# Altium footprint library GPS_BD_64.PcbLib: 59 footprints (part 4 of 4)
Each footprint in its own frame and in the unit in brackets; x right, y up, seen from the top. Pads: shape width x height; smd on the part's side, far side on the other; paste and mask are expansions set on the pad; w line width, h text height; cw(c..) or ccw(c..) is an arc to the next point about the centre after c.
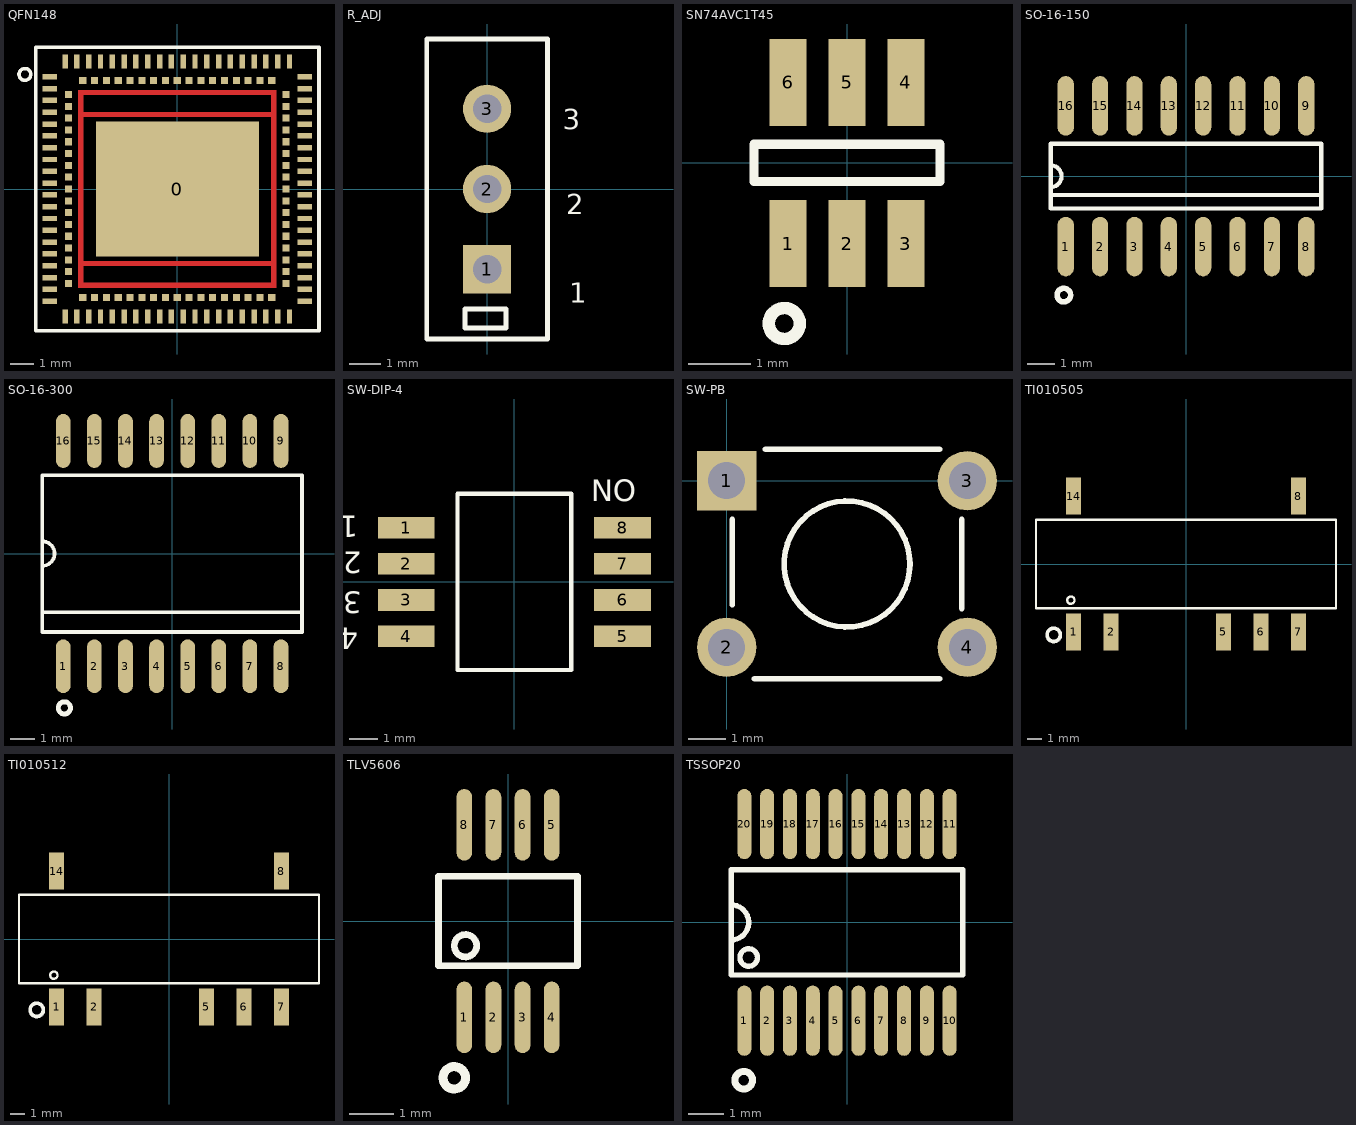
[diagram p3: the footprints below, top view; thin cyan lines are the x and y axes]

## QFN148 [mm]
height 11
pads (149):
  rect 6.9x5.7 smd: 0(0,0)
  rect 0.6x0.23 smd: A1(-5.4,4.75) A2(-5.4,4.25) A3(-5.4,3.75) A4(-5.4,3.25) A5(-5.4,2.75) A6(-5.4,2.25) A7(-5.4,1.75) A8(-5.4,1.25) A9(-5.4,0.75) A10(-5.4,0.25) A11(-5.4,-0.25) A12(-5.4,-0.75) A13(-5.4,-1.25) A14(-5.4,-1.75) A15(-5.4,-2.25) A16(-5.4,-2.75) A17(-5.4,-3.25) A18(-5.4,-3.75) A19(-5.4,-4.25) A20(-5.4,-4.75) A41(5.4,-4.75) A42(5.4,-4.25) A43(5.4,-3.75) A44(5.4,-3.25) A45(5.4,-2.75) A46(5.4,-2.25) A47(5.4,-1.75) A48(5.4,-1.25) A49(5.4,-0.75) A50(5.4,-0.25) A51(5.4,0.25) A52(5.4,0.75) A53(5.4,1.25) A54(5.4,1.75) A55(5.4,2.25) A56(5.4,2.75) A57(5.4,3.25) A58(5.4,3.75) A59(5.4,4.25) A60(5.4,4.75)
  rect 0.23x0.6 smd: A21(-4.75,-5.4) A22(-4.25,-5.4) A23(-3.75,-5.4) A24(-3.25,-5.4) A25(-2.75,-5.4) A26(-2.25,-5.4) A27(-1.75,-5.4) A28(-1.25,-5.4) A29(-0.75,-5.4) A30(-0.25,-5.4) A31(0.25,-5.4) A32(0.75,-5.4) A33(1.25,-5.4) A34(1.75,-5.4) A35(2.25,-5.4) A36(2.75,-5.4) A37(3.25,-5.4) A38(3.75,-5.4) A39(4.25,-5.4) A40(4.75,-5.4) A61(4.75,5.4) A62(4.25,5.4) A63(3.75,5.4) A64(3.25,5.4) A65(2.75,5.4) A66(2.25,5.4) A67(1.75,5.4) A68(1.25,5.4) A69(0.75,5.4) A70(0.25,5.4) A71(-0.25,5.4) A72(-0.75,5.4) A73(-1.25,5.4) A74(-1.75,5.4) A75(-2.25,5.4) A76(-2.75,5.4) A77(-3.25,5.4) A78(-3.75,5.4) A79(-4.25,5.4) A80(-4.75,5.4)
  rect 0.3x0.3 smd: B1(-4.6,4) B2(-4.6,3.5) B3(-4.6,3) B4(-4.6,2.5) B5(-4.6,2) B6(-4.6,1.5) B7(-4.6,1) B8(-4.6,0.5) B9(-4.6,0) B10(-4.6,-0.5) B11(-4.6,-1) B12(-4.6,-1.5) B13(-4.6,-2) B14(-4.6,-2.5) B15(-4.6,-3) B16(-4.6,-3.5) B17(-4.6,-4) B18(-4,-4.6) B19(-3.5,-4.6) B20(-3,-4.6) B21(-2.5,-4.6) B22(-2,-4.6) B23(-1.5,-4.6) B24(-1,-4.6) B25(-0.5,-4.6) B26(0,-4.6) B27(0.5,-4.6) B28(1,-4.6) B29(1.5,-4.6) B30(2,-4.6) B31(2.5,-4.6) B32(3,-4.6) B33(3.5,-4.6) B34(4,-4.6) B35(4.6,-4) B36(4.6,-3.5) B37(4.6,-3) B38(4.6,-2.5) B39(4.6,-2) B40(4.6,-1.5) B41(4.6,-1) B42(4.6,-0.5) B43(4.6,0) B44(4.6,0.5) B45(4.6,1) B46(4.6,1.5) B47(4.6,2) B48(4.6,2.5) B49(4.6,3) B50(4.6,3.5) B51(4.6,4) B52(4,4.6) B53(3.5,4.6) B54(3,4.6) B55(2.5,4.6) B56(2,4.6) B57(1.5,4.6) B58(1,4.6) B59(0.5,4.6) B60(0,4.6) B61(-0.5,4.6) B62(-1,4.6) B63(-1.5,4.6) B64(-2,4.6) B65(-2.5,4.6) B66(-3,4.6) B67(-3.5,4.6) B68(-4,4.6)
Top Layer:
  rectangle: -4.2,-4.2 -3.97,4.2
  rectangle: -4.2,3.97 3.97,4.2
  rectangle: 3.97,-4.2 4.2,4.2
  rectangle: -4.2,-4.2 4.201,-3.969
  rectangle: -4.072,-3.25 4.056,-3.05
  rectangle: -4.047,3.05 4.056,3.25
  region: -4.2,-4.2 4.2,-4.2 -4.2,-4.2
Top Overlay:
  circle w0.15: c-6.45,4.85 r0.25
  lines w0.15: -6,-6 6,-6 6,6 -6,6 -6,-6
Top Paste:
  rectangle: -4.2,-4.2 -3.97,3.97
  rectangle: -4.2,3.97 3.97,4.2
  rectangle: 3.97,-3.97 4.2,4.2
  rectangle: -3.972,-4.198 4.199,-3.968
  rectangle: -3.972,-3.25 3.968,-3.05
  rectangle: -3.972,3.05 3.968,3.25
  region: -4.2,-4.2 4.2,-4.2 -4.2,-4.2
Top Solder:
  rectangle: -4.275,-3.895 -3.895,4.275
  rectangle: -4.275,-4.275 3.895,-3.895
  rectangle: 3.895,-4.275 4.275,3.895
  rectangle: -3.895,3.895 4.275,4.275
  rectangle: -3.895,2.975 3.895,3.325
  rectangle: -3.895,-3.325 3.895,-2.975

## R_ADJ [mil] "3290W"
height 390.16
pads (3):
  rect 60x60 hole 35.43: 1(0,-100)
  round 60 hole 35.43: 2(0,0) 3(0,100)
Top Overlay:
  lines w5.91: -75.2,-187.01 -75.2,187.01 75.2,187.01 75.2,-187.01 -75.2,-187.01 ; -27.56,-173.23 -27.56,-149.61 23.62,-149.61 23.62,-173.23 -27.56,-173.23
  text "3" at 94.49,74.8 h25
  text "2" at 98.43,-31.5 h25
  text "1" at 102.36,-141.73 h25

## SN74AVC1T45 [mm]
height 1.45
pads (6):
  rect 0.6x1.4 smd: 1(-0.95,-1.3) 2(0,-1.3) 3(0.95,-1.3) 4(0.95,1.3) 5(0,1.3) 6(-0.95,1.3)
Top Overlay:
  circle w0.2: c-1.012,-2.591 r0.25
  lines w0.15: -1.5,-0.3 -1.5,0.3 1.5,0.3 1.5,-0.3 -1.5,-0.3

## SO-16-150 [mm]
height 11
pads (16):
  oval 0.6x2.2 smd: 1(-4.445,-2.6) 2(-3.175,-2.6) 3(-1.905,-2.6) 4(-0.635,-2.6) 5(0.635,-2.6) 6(1.905,-2.6) 7(3.175,-2.6) 8(4.445,-2.6) 9(4.445,2.6) 10(3.175,2.6) 11(1.905,2.6) 12(0.635,2.6) 13(-0.635,2.6) 14(-1.905,2.6) 15(-3.175,2.6) 16(-4.445,2.6)
Top Overlay:
  circle w0.2: c-4.517,-4.394 r0.25
  lines w0.15: -5,-0.7 5,-0.7 ; -5,-0.4 ccw(c-5,0) -5,0.4 ; -5,-1.2 5,-1.2 5,1.2 -5,1.2 -5,-1.2

## SO-16-300 [mm]
height 11
pads (16):
  oval 0.6x2.2 smd: 1(-4.445,-4.6) 2(-3.175,-4.6) 3(-1.905,-4.6) 4(-0.635,-4.6) 5(0.635,-4.6) 6(1.905,-4.6) 7(3.175,-4.6) 8(4.445,-4.6) 9(4.445,4.6) 10(3.175,4.6) 11(1.905,4.6) 12(0.635,4.6) 13(-0.635,4.6) 14(-1.905,4.6) 15(-3.175,4.6) 16(-4.445,4.6)
Top Overlay:
  circle w0.2: c-4.4,-6.3 r0.25
  lines w0.15: -5.3,-2.4 5.3,-2.4 ; -5.3,-0.5 ccw(c-5.3,0) -5.3,0.5 ; -5.3,-3.2 -5.3,3.2 5.3,3.2 5.3,-3.2 -5.3,-3.2

## SW-DIP-4 [mm]
height 11
pads (8):
  rect 2x0.76 smd: 1(-3.8,1.905) 2(-3.8,0.635) 3(-3.8,-0.635) 4(-3.8,-1.905) 5(3.8,-1.905) 6(3.8,-0.635) 7(3.8,0.635) 8(3.8,1.905)
Top Overlay:
  lines w0.15: -2,-3.1 2,-3.1 2,3.1 -2,3.1 -2,-3.1
  text "ON" at 4.283,3.595 h0.76
  text "4" at -5.496,-1.612 h0.76
  text "3" at -5.369,-0.342 h0.76
  text "2" at -5.369,1.055 h0.76
  text "1" at -5.496,2.325 h0.76

## SW-PB [mm]
height 11
pads (4):
  rect 1.6x1.6 hole 1: 1(0,0)
  round 1.6 hole 1: 2(0,-4.5) 3(6.5,0) 4(6.5,-4.5)
Top Overlay:
  circle w0.152: c3.25,-2.25 r1.7
  lines w0.155: 0.15,-3.35 0.15,-1.05 ; 0.75,-5.35 5.75,-5.35 ; 1.05,0.85 5.75,0.85 ; 6.35,-3.45 6.35,-1.05

## TI010505 [mm]
height 1.45
pads (7):
  rect 1x2.5 smd: 1(-7.62,-4.6) 2(-5.08,-4.6) 5(2.54,-4.6) 6(5.08,-4.6) 7(7.62,-4.6) 8(7.62,4.6) 14(-7.62,4.6)
Top Overlay:
  circle w0.25: c-8.959,-4.801 r0.45
  circle w0.152: c-7.8,-2.45 r0.25
  lines w0.155: -10.16,-3 -10.16,3 10.16,3 10.16,-3 -10.16,-3

## TI010512 [mm]
height 1.45
pads (7):
  rect 1x2.5 smd: 1(-7.62,-4.6) 2(-5.08,-4.6) 5(2.54,-4.6) 6(5.08,-4.6) 7(7.62,-4.6) 8(7.62,4.6) 14(-7.62,4.6)
Top Overlay:
  circle w0.25: c-8.959,-4.801 r0.45
  circle w0.152: c-7.8,-2.45 r0.25
  lines w0.155: -10.16,-3 -10.16,3 10.16,3 10.16,-3 -10.16,-3

## TLV5606 [mm]
height 1.45
pads (8):
  oval 0.35x1.6 smd: 1(-0.975,-2.15) 2(-0.325,-2.15) 3(0.325,-2.15) 4(0.975,-2.15) 5(0.975,2.15) 6(0.325,2.15) 7(-0.325,2.15) 8(-0.975,2.15)
Top Overlay:
  circle w0.2: c-1.2,-3.5 r0.25
  circle w0.15: c-0.95,-0.55 r0.25
  lines w0.15: -1.55,-1 -1.55,1 1.55,1 1.55,-1 -1.55,-1

## TSSOP20 [mm]
height 11
pads (20):
  oval 0.4x2 smd: 1(-2.925,-2.8) 2(-2.275,-2.8) 3(-1.625,-2.8) 4(-0.975,-2.8) 5(-0.325,-2.8) 6(0.325,-2.8) 7(0.975,-2.8) 8(1.625,-2.8) 9(2.275,-2.8) 10(2.925,-2.8) 11(2.925,2.8) 12(2.275,2.8) 13(1.625,2.8) 14(0.975,2.8) 15(0.325,2.8) 16(-0.325,2.8) 17(-0.975,2.8) 18(-1.625,2.8) 19(-2.275,2.8) 20(-2.925,2.8)
Top Overlay:
  circle w0.15: c-2.8,-1 r0.25
  circle w0.2: c-2.942,-4.496 r0.25
  lines w0.15: -3.3,-0.5 ccw(c-3.3,0) -3.3,0.5 ; -3.3,-1.5 3.3,-1.5 3.3,1.5 -3.3,1.5 -3.3,-1.5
